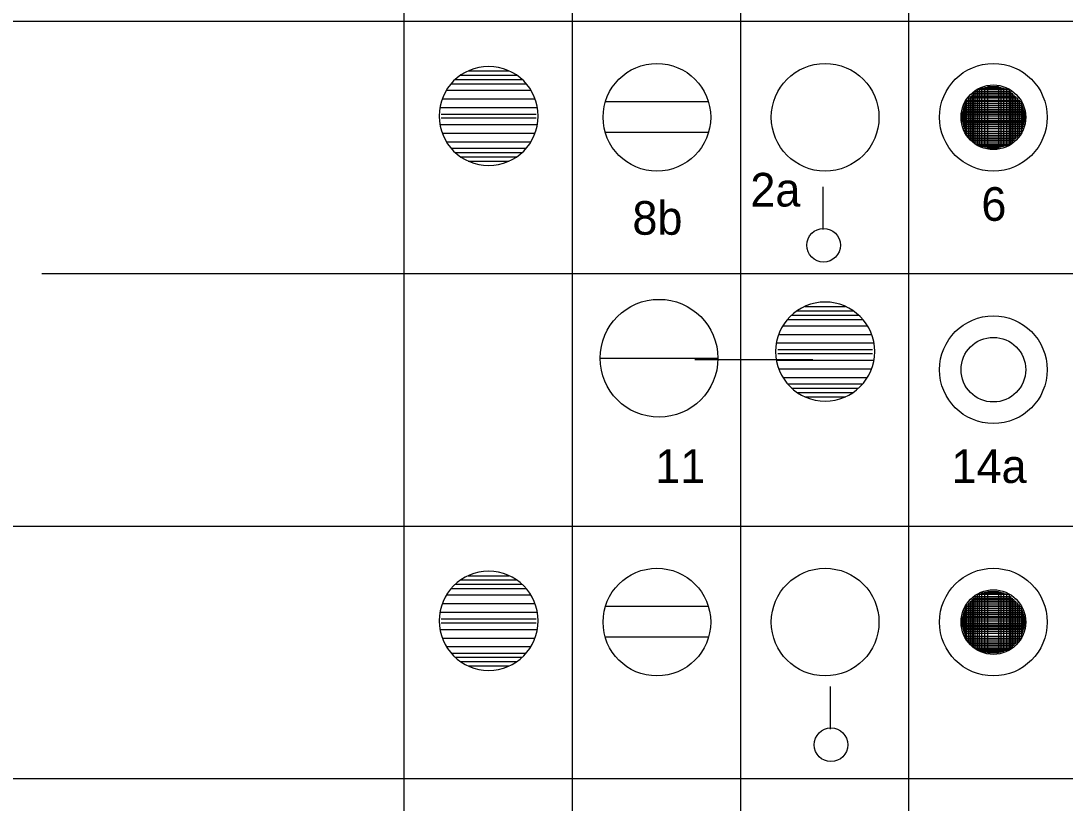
# Model space of a CAD drawing. Extents: x -28 to 822, y 61 to 665.
# Drawn here: x 337.9 to 399.9, y 200.3 to 246.8 of the extents above; entities that cross this region are included whole.
import ezdxf

# ---------------------------------------------------------------- set-up
doc = ezdxf.new("R2010")
doc.units = 0
doc.layers.add('KOLEJIŠTĚ', color=7, linetype='Continuous')

# ---------------------------------------------------------------- blocks, each defined once
blk = doc.blocks.new('HR6')
for p, q in [((-0.95, 2.095), (0.95, 2.095)), ((-1.748, 1.495), (1.748, 1.495)), ((-1.555, 1.695), (1.555, 1.695)), ((-1.304, 1.895), (1.304, 1.895)), ((-1.962, 1.2), (1.962, 1.2)), ((-2.156, 0.8), (2.156, 0.8)), ((-2.265, 0.4), (2.265, 0.4)), ((-2.2, 0.09), (2.2, 0.09)), ((-2.265, -0.4), (2.265, -0.4)), ((-2.2, -0.09), (2.2, -0.09)), ((-2.156, -0.8), (2.156, -0.8)), ((-1.962, -1.2), (1.962, -1.2)), ((-1.748, -1.495), (1.748, -1.495)), ((-1.555, -1.695), (1.555, -1.695)), ((-1.304, -1.895), (1.304, -1.895)), ((-0.95, -2.095), (0.95, -2.095))]:
    blk.add_line(p, q)
for start, end in [(0, 180), (180, 0)]:
    blk.add_arc((0, 0), 2.3, start, end)
blk = doc.blocks.new('ZT75')
at = {"xscale": 0.8, "yscale": 0.8000000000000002}
blk.add_blockref('HR6', (0, 0), dxfattribs=at)
blk = doc.blocks.new('HR3')
for radius in [2.5, 1.5]:
    blk.add_circle((0, 0), radius)
blk = doc.blocks.new('ZT72')
at = {"xscale": 0.8, "yscale": 0.8000000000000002}
blk.add_blockref('HR3', (0, 0), dxfattribs=at)
blk = doc.blocks.new('HR1')
blk.add_line((-2.5, 0), (2.5, 0))
blk.add_circle((0, 0), 2.5)

msp = doc.modelspace()

# ---------------------------------------------------------------- linework, layer by layer
for p, q in [((360.616, 381.738), (360.616, 111.738)), ((370.616, 381.738), (370.616, 111.738)), ((380.616, 381.738), (380.616, 111.738)), ((390.616, 381.738), (390.616, 111.738)), ((5.068, 246.738), (540.616, 246.738)), ((5.068, 246.738), (540.616, 246.738)), ((378.72, 241.957), (372.594, 241.957)), ((378.727, 240.126), (372.588, 240.126)), ((385.532, 234.364), (385.532, 236.897)), ((339.087, 231.738), (540.616, 231.738)), ((384.925, 226.611), (377.92, 226.611)), ((5.068, 216.738), (540.616, 216.738)), ((378.72, 211.957), (372.594, 211.957)), ((378.727, 210.126), (372.588, 210.126)), ((385.972, 204.675), (385.972, 207.208)), ((5.068, 201.738), (540.616, 201.738)), ((5.068, 201.738), (540.616, 201.738)), ((5.068, 201.738), (540.616, 201.738)), ((54.092, 201.738), (540.616, 201.738))]:
    msp.add_line(p, q)
for points in [[(396.601, 239.383), (394.708, 239.383), (394.708, 242.692), (396.601, 242.692)], [(396.437, 239.337), (394.826, 239.337), (394.826, 242.719), (396.437, 242.719)], [(396.264, 239.292), (394.972, 239.292), (394.972, 242.765), (396.264, 242.765)], [(396.109, 239.246), (395.145, 239.246), (395.145, 242.81), (396.109, 242.81)], [(395.955, 239.201), (395.336, 239.201), (395.336, 242.856), (395.955, 242.856)], [(397.092, 239.846), (394.198, 239.846), (394.198, 242.183), (397.092, 242.183)], [(396.965, 239.746), (394.299, 239.746), (394.299, 242.274), (396.965, 242.274)], [(396.865, 239.646), (394.39, 239.646), (394.39, 242.365), (396.865, 242.365)], [(396.774, 239.546), (394.471, 239.546), (394.471, 242.456), (396.774, 242.456)], [(396.665, 239.437), (394.572, 239.437), (394.572, 242.556), (396.665, 242.556)], [(397.438, 240.583), (393.871, 240.583), (393.871, 241.501), (397.438, 241.501)], [(397.411, 240.474), (393.907, 240.474), (393.907, 241.61), (397.411, 241.61)], [(397.374, 240.355), (393.935, 240.355), (393.935, 241.728), (397.374, 241.728)], [(397.329, 240.183), (393.971, 240.183), (393.971, 241.847), (397.329, 241.847)], [(397.302, 240.064), (394.007, 240.064), (394.007, 241.965), (397.302, 241.965)], [(397.183, 239.955), (394.071, 239.955), (394.071, 242.056), (397.183, 242.056)], [(397.547, 240.956), (393.78, 240.956), (393.78, 241.11), (397.547, 241.11)], [(397.484, 240.765), (393.807, 240.765), (393.807, 241.319), (397.484, 241.319)], [(397.511, 240.846), (393.807, 240.846), (393.807, 241.219), (397.511, 241.219)], [(397.465, 240.674), (393.853, 240.674), (393.853, 241.392), (397.465, 241.392)], [(396.865, 209.646), (394.39, 209.646), (394.39, 212.365), (396.865, 212.365)], [(396.774, 209.546), (394.471, 209.546), (394.471, 212.456), (396.774, 212.456)], [(396.665, 209.437), (394.572, 209.437), (394.572, 212.556), (396.665, 212.556)], [(396.601, 209.383), (394.708, 209.383), (394.708, 212.692), (396.601, 212.692)], [(396.437, 209.337), (394.826, 209.337), (394.826, 212.719), (396.437, 212.719)], [(396.264, 209.292), (394.972, 209.292), (394.972, 212.765), (396.264, 212.765)], [(396.109, 209.246), (395.145, 209.246), (395.145, 212.81), (396.109, 212.81)], [(395.955, 209.201), (395.336, 209.201), (395.336, 212.856), (395.955, 212.856)], [(397.374, 210.355), (393.935, 210.355), (393.935, 211.728), (397.374, 211.728)], [(397.329, 210.183), (393.971, 210.183), (393.971, 211.847), (397.329, 211.847)], [(397.302, 210.064), (394.007, 210.064), (394.007, 211.965), (397.302, 211.965)], [(397.183, 209.955), (394.071, 209.955), (394.071, 212.056), (397.183, 212.056)], [(397.092, 209.846), (394.198, 209.846), (394.198, 212.183), (397.092, 212.183)], [(396.965, 209.746), (394.299, 209.746), (394.299, 212.274), (396.965, 212.274)], [(397.547, 210.956), (393.78, 210.956), (393.78, 211.11), (397.547, 211.11)], [(397.484, 210.765), (393.807, 210.765), (393.807, 211.319), (397.484, 211.319)], [(397.511, 210.846), (393.807, 210.846), (393.807, 211.219), (397.511, 211.219)], [(397.465, 210.674), (393.853, 210.674), (393.853, 211.392), (397.465, 211.392)], [(397.438, 210.583), (393.871, 210.583), (393.871, 211.501), (397.438, 211.501)], [(397.411, 210.474), (393.907, 210.474), (393.907, 211.61), (397.411, 211.61)]]:
    msp.add_lwpolyline(points, close=True)
for centre, radius in [((375.657, 241.031), 3.2), ((385.657, 241.031), 3.2), ((385.564, 233.428), 1), ((375.657, 211.031), 3.2), ((385.657, 211.031), 3.2), ((386.004, 203.739), 1)]:
    msp.add_circle(centre, radius)

# ---------------------------------------------------------------- block references
at = {"xscale": 1.4000000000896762, "yscale": 1.4000000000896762}
msp.add_blockref('HR1', (375.783, 226.712), dxfattribs=at)
at = {"layer": 'KOLEJIŠTĚ', "xscale": 1.600000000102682, "yscale": 1.600000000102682}
for name, p in [('ZT75', (365.657, 241.107)), ('ZT72', (395.657, 241.031)), ('ZT75', (385.657, 227.106)), ('ZT72', (395.657, 226.031)), ('ZT72', (395.657, 211.031)), ('ZT75', (365.657, 211.107))]:
    msp.add_blockref(name, p, dxfattribs=at)

# ---------------------------------------------------------------- texts
for s, p in [('2a', (381.212, 235.727)), ('6', (394.944, 234.878)), ('8b', (374.2, 234.052)), ('11', (375.554, 219.301)), ('14a', (393.166, 219.301))]:
    msp.add_text(s, height=2).set_placement(p)

doc.saveas('drawing.dxf')
